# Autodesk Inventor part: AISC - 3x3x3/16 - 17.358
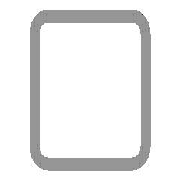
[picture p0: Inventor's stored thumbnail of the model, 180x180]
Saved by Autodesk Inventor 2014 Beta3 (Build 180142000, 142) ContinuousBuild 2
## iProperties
_CCFamilyMember: 9
_CCFamilyDisplayName: ANSI AISC (Square) - Tube
_FrameMemberDoc: Frame Member File
_Version: 15.0.0
_GetPNFromCC: 1
Created: 2011-11
Part Number: AISC - 3x3x3/16 - 17.358
Material: Steel, Mild
Description: Tube
Document SubType Name: Modeling
Standard: ANSI
Designer: Thom Tremblay
Standards Organization: ANSI
Language: en-US
Size Designation: 3x3x3/16
Categories: <MemberInstance><Categories><Category DisplayName="Structural Shapes" InternalName="089c4875-fa83-4c05-b084-43b9cc11f5ed" Mnemonic="GRDR"><CategoryParameter Dis
Stock Number: 3x3x3/16
Density: 7.86 g/cm^3
Appearance: Steel
IsCustomPart: 1
G_L: 17.358 in
G_W: 3.000 in
G_H: 3.000 in
+FBB95EFE-D9FF-42D0-8AC8-0864100EF564+CUTDETAIL3: Cut
+4579BF79-A21E-4565-B507-9C500E28FE3C+CUTDETAIL4: Cut
Author: Thom Tremblay
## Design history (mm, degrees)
node "Start plane"
node "End plane"
node "Driven Length"
  sketch "Sketch3"
    geometry: L1 (0, 0)-(10, 0) reference
    constraints: 2 end point, 1 horizontal
  workplane "Work Plane3"
  sketch "Sketch4"
    geometry: L1 (-2, 0)-(12, 0) reference; L2 (-53.343, 440.904)-(53.343, 440.904) reference
    dimensions: "d19" = 440.90386 distance between parallel lines of L1 L2 (derived)
sketch "Sweep Path"
  geometry: L1 through (609.6, 0) direction (1, 0); 1 other entity
  constraints: 5 horizontal
node "Orientation Work Plane"
feature "Body" dims "d20" = 0
workplane "Work Plane7"
sketch "Sketch7"
  geometry: L1 (-38.6, 38.6)-(38.6, 38.6); L2 (-38.6, -38.6)-(38.6, -38.6)
  constraints: 4 end point
feature "LoftSrf3" sketch "Sketch7" dims "d29" = 0, "d30" = 90 deg, "d31" = 0, "d32" = 90 deg
split "Split3"
workplane "Work Plane8"
sketch "Sketch8"
  geometry: L1 (-38.6, 38.6)-(38.6, 38.6); L2 (-38.6, -38.6)-(38.6, -38.6)
  constraints: 4 end point
feature "LoftSrf4" sketch "Sketch8" dims "d33" = 0, "d34" = 90 deg, "d35" = 0, "d36" = 90 deg
split "Split4"
workplane "Work Plane9"
sketch "Sketch9"
  geometry: L1 (-38.6, 44.506)-(38.6, 44.506); L2 (-38.6, -44.506)-(38.6, -44.506)
  constraints: 4 end point
feature "LoftSrf5" sketch "Sketch9" dims "d37" = 0, "d38" = 90 deg, "d39" = 0, "d40" = 90 deg
split "Split5"
workplane "Work Plane10"
sketch "Sketch10"
  geometry: L1 (-38.6, 44.506)-(38.6, 44.506); L2 (-38.6, -44.506)-(38.6, -44.506)
  constraints: 4 end point
feature "LoftSrf6" sketch "Sketch10" dims "d41" = 0, "d42" = 90 deg, "d43" = 0, "d44" = 90 deg
split "Split6"
body "Solid1"
sketch "Sketch"
  geometry: L1 (-38.1, -28.575)-(-38.1, 28.575); L2 (-28.575, 38.1)-(28.575, 38.1); L3 (38.1, 28.575)-(38.1, -28.575); L4 (28.575, -38.1)-(-28.575, -38.1); L5 (-28.575, 33.337)-(28.575, 33.338); L6 (33.338, 28.575)-(33.338, -28.575); L7 (28.575, -33.337)-(-28.575, -33.338); L8 (-33.338, -28.575)-(-33.338, 28.575); L9 (0, 36.948)-(0, -36.948); L10 (-23.079, 0)-(23.079, 0); A1 r 9.525 centre (-28.575, -28.575) between (-38.1, -28.575) and (-28.575, -38.1); A2 r 9.525 centre (-28.575, 28.575) between (-28.575, 38.1) and (-38.1, 28.575); A3 r 9.525 centre (28.575, 28.575) between (38.1, 28.575) and (28.575, 38.1); A4 r 9.525 centre (28.575, -28.575) between (28.575, -38.1) and (38.1, -28.575); A5 r 4.763 centre (-28.575, 28.575) between (-28.575, 33.337) and (-33.338, 28.575); A6 r 4.763 centre (28.575, 28.575) between (33.338, 28.575) and (28.575, 33.338); A7 r 4.763 centre (28.575, -28.575) between (28.575, -33.337) and (33.338, -28.575); A8 r 4.763 centre (-28.575, -28.575) between (-33.338, -28.575) and (-28.575, -33.338)
  constraints: 20 end point, 16 point on circle, 8 centre point, 8 tangent, 4 parallel, 3 equal radius, 2 perpendicular, 7 other
  dimensions: "d10" = 76.2 distance between parallel lines of L2 L4 (= G_H); "d11" = 76.2 distance between parallel lines of L1 L3 (= G_W); "d12" = 4.7625 distance between parallel lines of L3 L6 (= G_T); "d15" = 38.1 distance between parallel lines of L2 L10 (= 0.5 x d10); "d16" = 38.1 distance between parallel lines of L9 L3 (= 0.5 x d11); "d17" = 9.525 radius of A1 (= G_IR)
body "Srf3"
body "Srf4"
body "Srf5"
body "Srf6"
other parameters: "G_W" = 76.2 [user parameter; used in 1 equation term], "G_H" = 76.2 [user parameter; used in 1 equation term], "G_T" = 4.7625 [user parameter; used in 1 equation term], "G_IR" = 9.525 [user parameter; used in 1 equation term], "G_L" = 440.90386 (= d19) [user parameter], "G_OFFSET_START" = 0 [user parameter; used in 1 equation term], "G_OFFSET_END" = 0 [user parameter; used in 1 equation term], "d13" = 0 (computed from G_OFFSET_START), "d14" = 440.90386 (= G_OFFSET_END + B_L), "B_L" = 440.90386 [user parameter; used in 1 equation term], "d18" = 90 deg
